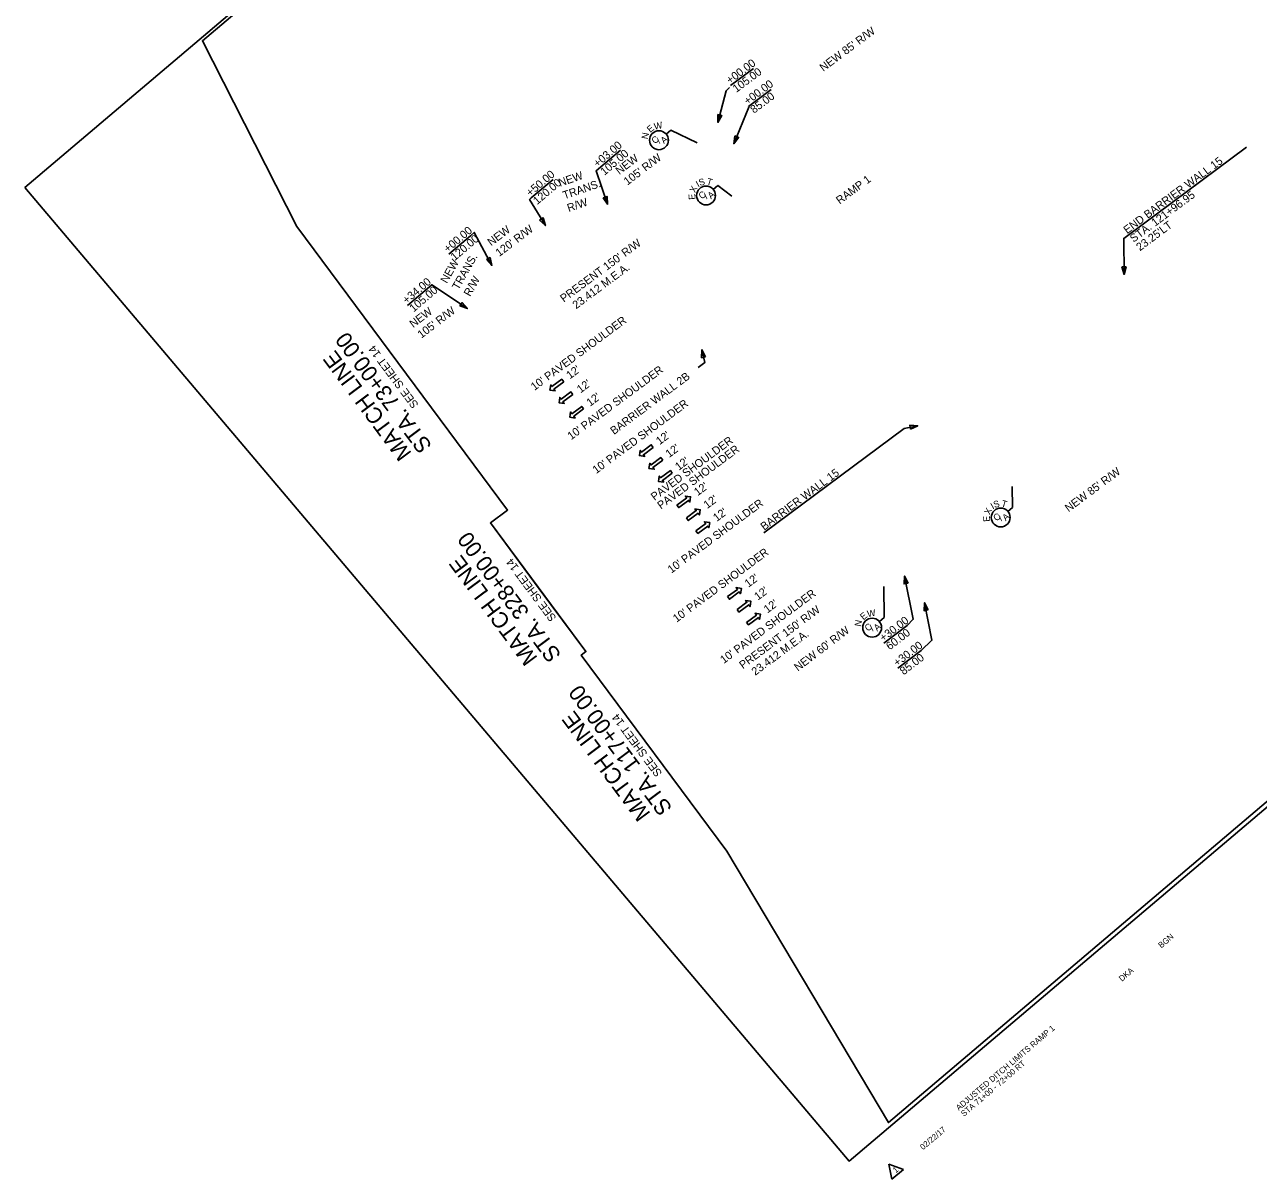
# Model space of a CAD drawing. Extents: x 1613433 to 1615331, y 1095338 to 1097615.
# Drawn here: x 1613433 to 1614358, y 1095710 to 1096576 of the extents above; entities that cross this region are included whole.
import ezdxf

# ---------------------------------------------------------------- set-up
doc = ezdxf.new("R2010")
doc.units = 0
for name, color, linetype in [('RD_EX_Bldg', 7, 'Continuous'), ('RD_EX_BldgApp_txCode', 7, 'Continuous'), ('RD_EX_DR_Pipe', 7, 'Continuous'), ('RD_EX_DV_Prop', 7, 'Continuous'), ('RD_EX_Fence_ChLk', 7, 'Continuous'), ('RD_EX_GuardRail', 7, 'Continuous'), ('RD_EX_RW', 7, 'Continuous'), ('RD_HC_TX_Rel_Sta50', 7, 'Continuous'), ('RD_PD_RW_TX', 7, 'Continuous'), ('RD_SHT_DR_TX_FINAL', 7, 'Continuous'), ('RD_SHT_UT_TX_PREL', 7, 'Continuous')]:
    doc.layers.add(name, color=color, linetype=linetype)

msp = doc.modelspace()

# ---------------------------------------------------------------- linework, layer by layer
at = {"layer": 'RD_EX_Bldg'}
for p, q in [((1613979.15, 1096542.91), (1613961.91, 1096530.1)), ((1613992.35, 1096527.26), (1613975.17, 1096514.5)), ((1613879.32, 1096481.76), (1613862.74, 1096467.71)), ((1613828.71, 1096459.69), (1613812.33, 1096445.81)), ((1613766.74, 1096417.54), (1613750.48, 1096403.77)), ((1613736.07, 1096379.21), (1613719.62, 1096365.27)), ((1614094.31, 1096125.36), (1614076.89, 1096112.07)), ((1614104.72, 1096106.68), (1614087.37, 1096093.44))]:
    msp.add_line(p, q, dxfattribs=at)
for points in [[(1613961.07, 1096528.71), (1613958.44, 1096526.26), (1613952.34, 1096502.51)], [(1613975.17, 1096514.5), (1613975.58, 1096513.95), (1613964.27, 1096486.46)], [(1613862.74, 1096467.71), (1613860.95, 1096466.2), (1613869.67, 1096441.06)], [(1613812.33, 1096445.81), (1613811.11, 1096444.78), (1613823.01, 1096425.06)], [(1613766.74, 1096417.54), (1613769.59, 1096419.96), (1613782.88, 1096395.23)], [(1613736.07, 1096379.21), (1613737.91, 1096380.76), (1613764.54, 1096362.91)], [(1614094.31, 1096125.36), (1614098.86, 1096129.95), (1614092.39, 1096162.41)], [(1614104.72, 1096106.68), (1614112.82, 1096114.27), (1614107.31, 1096142.35)]]:
    msp.add_lwpolyline(points, dxfattribs=at)
for points in [[(1613952.27, 1096508.51), (1613952.34, 1096502.51), (1613955.28, 1096507.73)], [(1613965.04, 1096492.41), (1613964.27, 1096486.46), (1613967.91, 1096491.23)], [(1613866.31, 1096446.03), (1613869.67, 1096441.06), (1613869.24, 1096447.04)], [(1613818.68, 1096429.22), (1613823.01, 1096425.06), (1613821.34, 1096430.82)], [(1613778.77, 1096399.6), (1613782.88, 1096395.23), (1613781.5, 1096401.07)], [(1613758.86, 1096364.84), (1613764.54, 1096362.91), (1613760.59, 1096367.42)], [(1614095.05, 1096157.03), (1614092.39, 1096162.41), (1614092, 1096156.42)], [(1614109.95, 1096136.96), (1614107.31, 1096142.35), (1614106.9, 1096136.36)]]:
    msp.add_lwpolyline(points, close=True, dxfattribs=at)
at = {"layer": 'RD_EX_BldgApp_txCode'}
for p, q in [((1613913.58, 1096493.68), (1613917.07, 1096496.64)), ((1613917.07, 1096496.64), (1613936.78, 1096487.21)), ((1614076.91, 1096131.23), (1614076.74, 1096154.51)), ((1614073.41, 1096128.27), (1614076.91, 1096131.23))]:
    msp.add_line(p, q, dxfattribs=at)
for centre in [(1613908.17, 1096489.1), (1614068.01, 1096123.69)]:
    msp.add_circle(centre, 7.08, dxfattribs=at)
at = {"layer": 'RD_EX_DR_Pipe'}
msp.add_lwpolyline([(1613636.52, 1096424.5), (1613794.63, 1096211.8), (1613781.72, 1096202.21), (1613853.42, 1096105.74), (1613849.89, 1096103.11), (1613959.14, 1095956.14), (1614080.2, 1095752.68), (1615305.34, 1096791.88), (1615113.55, 1096967.95), (1614971.19, 1097080.18), (1614985.17, 1097098.15), (1614915.33, 1097153.87), (1614938.71, 1097183.17), (1614788.78, 1097308.44), (1614642.53, 1097430.66), (1614558.88, 1097359.26), (1614537.15, 1097384.71), (1613565.82, 1096563.64)], close=True, dxfattribs=at)
msp.add_lwpolyline([(1613636.52, 1096424.5), (1613794.63, 1096211.8), (1613781.72, 1096202.21), (1613853.42, 1096105.74), (1613849.89, 1096103.11), (1613959.14, 1095956.14), (1614080.2, 1095752.68), (1615305.34, 1096791.88), (1615113.55, 1096967.95), (1614971.19, 1097080.18), (1614985.17, 1097098.15), (1614915.33, 1097153.87), (1614938.71, 1097183.17), (1614788.78, 1097308.44), (1614642.53, 1097430.66), (1614558.88, 1097359.26), (1614537.15, 1097384.71), (1613565.82, 1096563.64)], close=True, dxfattribs=at)
at = {"layer": 'RD_EX_Fence_ChLk'}
for p, q in [((1613948.87, 1096452.28), (1613952.36, 1096455.24)), ((1613952.36, 1096455.24), (1613962.89, 1096447.12)), ((1614173.31, 1096213.82), (1614172.95, 1096229.46)), ((1614169.81, 1096210.86), (1614173.31, 1096213.82))]:
    msp.add_line(p, q, dxfattribs=at)
for centre in [(1613943.46, 1096447.7), (1614164.41, 1096206.28)]:
    msp.add_circle(centre, 7.08, dxfattribs=at)
at = {"layer": 'RD_EX_GuardRail'}
msp.add_lwpolyline([(1613432.53, 1096453.7), (1614710.66, 1097536.29), (1615328.87, 1096806.42), (1614050.74, 1095723.83)], close=True, dxfattribs=at)
at = {"layer": 'RD_EX_RW'}
for points in [[(1613836.71, 1096307.94), (1613835.28, 1096309.86), (1613827.92, 1096304.39), (1613826.95, 1096305.7), (1613826.37, 1096301.74), (1613830.32, 1096301.16), (1613829.35, 1096302.46)], [(1613843.56, 1096298.55), (1613842.12, 1096300.47), (1613834.76, 1096295), (1613833.79, 1096296.31), (1613833.21, 1096292.35), (1613837.17, 1096291.77), (1613836.19, 1096293.07)], [(1613851.68, 1096287.62), (1613850.24, 1096289.55), (1613842.88, 1096284.08), (1613841.91, 1096285.38), (1613841.33, 1096281.43), (1613845.29, 1096280.84), (1613844.31, 1096282.15)], [(1613903.83, 1096258.83), (1613902.39, 1096260.76), (1613895.03, 1096255.29), (1613894.06, 1096256.6), (1613893.48, 1096252.64), (1613897.44, 1096252.06), (1613896.46, 1096253.36)], [(1613910.98, 1096249.2), (1613909.55, 1096251.13), (1613902.19, 1096245.66), (1613901.22, 1096246.97), (1613900.64, 1096243.01), (1613904.59, 1096242.43), (1613903.62, 1096243.73)], [(1613918.14, 1096239.57), (1613916.71, 1096241.5), (1613909.35, 1096236.03), (1613908.38, 1096237.33), (1613907.8, 1096233.38), (1613911.75, 1096232.79), (1613910.78, 1096234.1)], [(1613921.57, 1096215.58), (1613923.01, 1096213.65), (1613930.37, 1096219.12), (1613931.34, 1096217.81), (1613931.92, 1096221.77), (1613927.96, 1096222.35), (1613928.94, 1096221.05)], [(1613928.73, 1096205.94), (1613930.16, 1096204.02), (1613937.53, 1096209.49), (1613938.5, 1096208.18), (1613939.08, 1096212.14), (1613935.12, 1096212.72), (1613936.09, 1096211.42)], [(1613935.89, 1096196.31), (1613937.32, 1096194.39), (1613944.68, 1096199.86), (1613945.66, 1096198.55), (1613946.24, 1096202.51), (1613942.28, 1096203.09), (1613943.25, 1096201.79)], [(1613959.57, 1096146.93), (1613961, 1096145), (1613968.36, 1096150.47), (1613969.34, 1096149.16), (1613969.92, 1096153.12), (1613965.96, 1096153.7), (1613966.93, 1096152.4)], [(1613966.73, 1096137.29), (1613968.16, 1096135.37), (1613975.52, 1096140.84), (1613976.49, 1096139.53), (1613977.08, 1096143.49), (1613973.12, 1096144.07), (1613974.09, 1096142.77)], [(1613973.89, 1096127.66), (1613975.32, 1096125.74), (1613982.68, 1096131.21), (1613983.65, 1096129.9), (1613984.24, 1096133.86), (1613980.28, 1096134.44), (1613981.25, 1096133.13)]]:
    msp.add_lwpolyline(points, close=True, dxfattribs=at)
at = {"layer": 'RD_SHT_DR_TX_FINAL'}
for p, q in [((1613794.63, 1096211.8), (1613636.52, 1096424.5)), ((1613849.89, 1096103.11), (1613959.14, 1095956.14))]:
    msp.add_line(p, q, dxfattribs=at)
msp.add_lwpolyline([(1613853.42, 1096105.74), (1613818.43, 1096152.82), (1613781.72, 1096202.21)], dxfattribs=at)
at = {"layer": 'RD_SHT_UT_TX_PREL'}
for p, q in [((1614348.68, 1096483.86), (1614259.8, 1096417.79)), ((1614080.53, 1095721.54), (1614091.43, 1095717.47)), ((1614080.53, 1095721.54), (1614082.74, 1095710.11)), ((1614082.74, 1095710.11), (1614091.43, 1095717.47))]:
    msp.add_line(p, q, dxfattribs=at)
for points in [[(1614259.8, 1096417.79), (1614256.63, 1096415.44), (1614256.97, 1096388.48)], [(1613937.54, 1096318.73), (1613942.48, 1096322.41), (1613940.31, 1096332)], [(1613986.84, 1096194.87), (1614091.91, 1096272.98), (1614102.24, 1096275.02)]]:
    msp.add_lwpolyline(points, dxfattribs=at)
for points in [[(1614255.34, 1096394.26), (1614256.97, 1096388.48), (1614258.45, 1096394.3)], [(1613943.1, 1096326.69), (1613940.31, 1096332), (1613940.07, 1096326)], [(1614096.86, 1096272.38), (1614102.24, 1096275.02), (1614096.26, 1096275.42)]]:
    msp.add_lwpolyline(points, close=True, dxfattribs=at)

# ---------------------------------------------------------------- texts
at = {"layer": 'RD_EX_Bldg'}
for s, rotation, p in [('+00.00', 36.62559, (1613961.38, 1096530.95)), ('105.00', 36.62559, (1613966.16, 1096524.53)), ('+00.00', 36.62559, (1613974.62, 1096515.33)), ('85.00', 36.62559, (1613979.39, 1096508.91)), ('+03.00', 40.26505, (1613862.1, 1096468.48)), ('105.00', 40.26505, (1613867.27, 1096462.37)), ('+50.00', 40.26505, (1613811.68, 1096446.58)), ('120.00', 40.26505, (1613816.85, 1096440.47)), ('+00.00', 40.26505, (1613749.83, 1096404.53)), ('120.00', 40.26505, (1613755, 1096398.43)), ('+34.00', 40.26505, (1613718.97, 1096366.04)), ('105.00', 40.26505, (1613724.14, 1096359.93)), ('+30.00', 37.32681, (1614076.36, 1096112.92)), ('60.00', 37.32681, (1614081.21, 1096106.56)), ('+30.00', 37.32681, (1614086.8, 1096094.27)), ('85.00', 37.32681, (1614091.65, 1096087.9))]:
    msp.add_text(s, height=6, rotation=rotation, dxfattribs=at).set_placement(p)
at = {"layer": 'RD_EX_BldgApp_txCode'}
for s, rotation, p in [('E', 40.26334, (1613901.66, 1096494.51)), ('W', 11.06439, (1613904.91, 1096496.9)), ('N', 79.17657, (1613899.84, 1096489.61)), ('C', 40.26342, (1613905.1, 1096485.99)), ('/', 40.26342, (1613908.72, 1096486.29)), ('A', 40.26342, (1613911.89, 1096486.16)), ('N', 79.17657, (1614059.67, 1096124.2)), ('E', 40.26334, (1614061.49, 1096129.1)), ('W', 11.06439, (1614064.75, 1096131.49)), ('C', 40.26342, (1614064.93, 1096120.58)), ('/', 40.26342, (1614068.55, 1096120.88)), ('A', 40.26342, (1614071.72, 1096120.75))]:
    msp.add_text(s, height=5, rotation=rotation, dxfattribs=at).set_placement(p)
at = {"layer": 'RD_EX_DV_Prop'}
for s, p in [("PRESENT 150' R/W ", (1613836.82, 1096367.29)), ('  23.412 M.E.A.', (1613842.48, 1096359.66)), ("PRESENT 150' R/W ", (1613971.09, 1096092.47)), ('  23.412 M.E.A.', (1613976.75, 1096084.85))]:
    msp.add_text(s, height=6, rotation=36.591, dxfattribs=at).set_placement(p)
at = {"layer": 'RD_EX_Fence_ChLk'}
for s, rotation, p in [('X', 63.40641, (1613935.23, 1096449.31)), ('I', 29.36118, (1613937.54, 1096453.64)), ('S', 17.64069, (1613938.87, 1096454.72)), ('T', 344.15357, (1613943.51, 1096456.09)), ('E', 95.21918, (1613935.61, 1096444.73)), ('C', 40.26179, (1613940.39, 1096444.59)), ('/', 40.26179, (1613944.01, 1096444.89)), ('A', 40.26179, (1613947.18, 1096444.76)), ('X', 63.40641, (1614156.17, 1096207.89)), ('I', 29.36118, (1614158.49, 1096212.22)), ('S', 17.64069, (1614159.82, 1096213.3)), ('T', 344.15357, (1614164.46, 1096214.66)), ('E', 95.21918, (1614156.56, 1096203.3)), ('C', 40.26179, (1614161.33, 1096203.16)), ('/', 40.26179, (1614164.95, 1096203.47)), ('A', 40.26179, (1614168.12, 1096203.33))]:
    msp.add_text(s, height=5, rotation=rotation, dxfattribs=at).set_placement(p)
at = {"layer": 'RD_HC_TX_Rel_Sta50'}
msp.add_text('RAMP 1', height=6, rotation=36.62559, dxfattribs=at).set_placement((1614043.71, 1096440.82))
at = {"layer": 'RD_PD_RW_TX'}
for s, rotation, p in [("NEW 85' R/W", 36.62559, (1614031.38, 1096540.33)), ('NEW ', 37.23548, (1613878.45, 1096463.01)), ("105' R/W", 37.23548, (1613884.5, 1096455.05)), ('NEW', 18.92517, (1613833.99, 1096454.2)), ('TRANS.', 18.92517, (1613837.24, 1096444.74)), ('R/W', 18.92517, (1613840.48, 1096435.28)), ('NEW ', 37.23548, (1613782.35, 1096409.49)), ("120' R/W", 37.23548, (1613788.4, 1096401.53)), ('NEW', 60.43154, (1613749.13, 1096381.35)), ('TRANS.', 60.43154, (1613757.83, 1096376.41)), ('R/W', 60.43154, (1613766.53, 1096371.48)), ('NEW ', 37.23548, (1613723.89, 1096348.22)), ("105' R/W", 37.23548, (1613729.94, 1096340.26)), ("NEW 85' R/W", 36.62559, (1614215.31, 1096210.08)), ("NEW 60' R/W", 37.23548, (1614012.34, 1096090.71))]:
    msp.add_text(s, height=6, rotation=rotation, dxfattribs=at).set_placement(p)
at = {"layer": 'RD_SHT_DR_TX_FINAL'}
for s, height, rotation, p in [('STA. 73+00.00', 12, 126.62559, (1613738.47, 1096260.16)), ('SEE SHEET 14', 6, 126.67686, (1613728.2, 1096290.89)), ('MATCH LINE', 12, 126.62559, (1613723.14, 1096254.41)), ('STA. 328+00.00', 12, 126.62559, (1613835.38, 1096103.37)), ('MATCH LINE', 12, 126.62559, (1613817.56, 1096100.99)), ('SEE SHEET 14', 6, 126.67686, (1613831.5, 1096131.1)), ('STA. 117+00.00', 12, 126.62559, (1613918.68, 1095988.51)), ('MATCH LINE', 12, 126.62559, (1613902.23, 1095984.26)), ('SEE SHEET 14', 6, 126.67686, (1613910.81, 1096014.69))]:
    msp.add_text(s, height=height, rotation=rotation, dxfattribs=at).set_placement(p)
at = {"layer": 'RD_SHT_UT_TX_PREL'}
for s, height, rotation, p in [('END BARRIER WALL 15', 6, 36.62559, (1614259.24, 1096418.63)), ('STA. 121+96.95', 6, 36.62559, (1614264.01, 1096412.21)), ("23.25'LT", 6, 36.62559, (1614268.78, 1096405.78)), ("10' PAVED SHOULDER", 6, 36.62397, (1613814.81, 1096301.15)), ("12'", 6, 36.62234, (1613841.37, 1096309.78)), ("10' PAVED SHOULDER", 6, 36.62397, (1613842.29, 1096264.13)), ('BARRIER WALL 2B', 6, 36.62722, (1613874.42, 1096268.07)), ("12'", 6, 36.62234, (1613849.32, 1096299.23)), ("12'", 6, 36.62234, (1613856.51, 1096289.25)), ("10' PAVED SHOULDER", 6, 36.62397, (1613861.12, 1096238.8)), ("12'", 6, 36.62234, (1613908.66, 1096260.46)), (' PAVED SHOULDER', 6, 36.62397, (1613903.05, 1096217.33)), (' PAVED SHOULDER', 6, 36.62397, (1613907.88, 1096210.84)), ("12'", 6, 36.62234, (1613915.82, 1096250.83)), ("12'", 6, 36.62234, (1613922.98, 1096241.2)), ('BARRIER WALL 15', 6, 36.62722, (1613987.05, 1096196.27)), ("12'", 6, 36.62234, (1613937.17, 1096222.18)), ("12'", 6, 36.62234, (1613944.33, 1096212.55)), ("10' PAVED SHOULDER", 6, 36.62397, (1613917.43, 1096164.09)), ("12'", 6, 36.62234, (1613951.49, 1096202.92)), ("10' PAVED SHOULDER", 6, 36.62397, (1613921.37, 1096127.33)), ("12'", 6, 36.62234, (1613975.17, 1096153.53)), ("10' PAVED SHOULDER", 6, 36.62397, (1613956.79, 1096096.44)), ("12'", 6, 36.62234, (1613982.33, 1096143.9)), ("12'", 6, 36.62234, (1613989.49, 1096134.27)), ('BGN', 4.4, 40.26505, (1614284.81, 1095883.16)), ('DKA', 4.4, 40.26505, (1614255.29, 1095858.15)), ('ADJUSTED DITCH LIMITS RAMP 1', 4.4, 40.26505, (1614133.07, 1095761.39)), ('STA 71+00 - 72+00 RT', 4.4, 40.26505, (1614136.86, 1095756.92)), ('02/22/17', 4.4, 40.26505, (1614106.22, 1095731.89)), ('1', 4.4, 40.26505, (1614085.73, 1095714.54))]:
    msp.add_text(s, height=height, rotation=rotation, dxfattribs=at).set_placement(p)

doc.saveas('drawing.dxf')
